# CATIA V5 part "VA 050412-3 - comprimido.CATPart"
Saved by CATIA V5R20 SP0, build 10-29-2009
Part number: VA 050412-3 - comprimido
Revision: ANY
Definition: UNKNOWN
Nomenclature: VA 050412-3 - comprimido
Source: Unknown
Bounding box of the stored display mesh (mm): x -1.312 to 1.312, y -0.125 to 3.875, z -1.312 to 1.312
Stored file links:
  C:\Users\Utente\Desktop\IO LAVORO\3D X SITO CF\CUMSA\3D files VA\VA 050412\VA 050412-3 - comprimido.CATPart
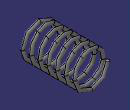
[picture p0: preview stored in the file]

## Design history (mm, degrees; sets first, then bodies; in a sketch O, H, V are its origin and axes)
Body1 "Revolución2" (main body)
  Solid1: solid without history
